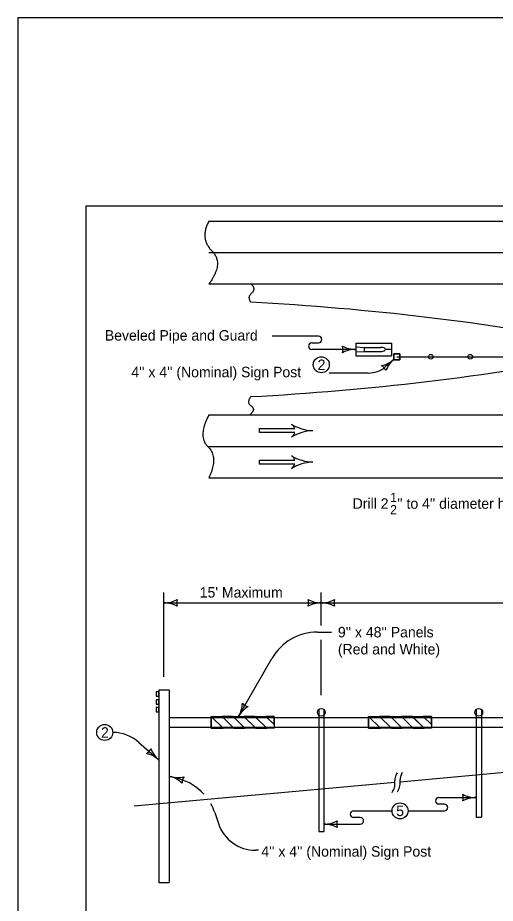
# Model space of a CAD drawing. Extents: x 228 to 3572, y -1307 to 1277.
# Drawn here: x 228 to 956, y -75 to 1277 of the extents above; entities that cross this region are included whole.
import ezdxf

# ---------------------------------------------------------------- set-up
doc = ezdxf.new("R2010")
doc.units = 0
for name, color, linetype in [('dsnShtPlotShapeBatchPrint', 7, 'Continuous'), ('dsnStdBorder', 7, 'Continuous'), ('dsnStdDimension', 7, 'Continuous'), ('Level 2', 7, 'Continuous'), ('Level 3', 7, 'Continuous')]:
    doc.layers.add(name, color=color, linetype=linetype)

msp = doc.modelspace()

# ---------------------------------------------------------------- linework, layer by layer
at = {"layer": 'dsnShtPlotShapeBatchPrint'}
msp.add_lwpolyline([(228, -1307), (3572, -1307), (3572, 1277), (228, 1277)], close=True, dxfattribs=at)
at = {"layer": 'dsnStdBorder'}
msp.add_lwpolyline([(332.5, 990), (3467.5, 990), (3467.5, -1020), (332.5, -1020)], close=True, dxfattribs=at)
at = {"layer": 'dsnStdDimension'}
for p, q in [((686.5, 791), (616.2, 791)), ((676.3, 780.9), (686.5, 780.9)), ((743.5, 770.7), (676.3, 770.7)), ((762.5, 734.6), (703, 734.6)), ((450.9, 270.8), (450.9, 399.9)), ((690.9, 349.5), (690.9, 399.9)), ((450.9, 383.9), (690.9, 383.9)), ((690.9, 383.9), (2130.9, 383.9)), ((685, 339.3), (706.4, 339.3)), ((690.9, 242.8), (690.9, 327.7)), ((564.7, 210.5), (615.6, 299.1)), ((412.7, 171), (442.9, 144.2)), ((870, 86.7), (926.9, 86.7)), ((878.5, 76.6), (868.4, 76.6)), ((528.4, 63.7), (534.1, 47)), ((740.2, 66.4), (798.6, 66.4)), ((750.3, 56.2), (740.2, 56.2)), ((823.1, 66.4), (878.5, 66.4)), ((694.9, 46.1), (750.3, 46.1))]:
    msp.add_line(p, q, dxfattribs=at)
for centre, radius, start, end in [((686.5, 786), 5.08, 270, 90), ((676.3, 775.8), 5.08, 90, 270), ((707.3, 770.7), 16.7, 342.2667, 17.7334), ((743.5, 813.9), 43.2, 241.9275, 270), ((743.5, 727.5), 43.2, 90, 118.0725), ((762.5, 774.6), 40, 270, 311.3965), ((772.8, 787.9), 43.2, 283.3279, 311.4004), ((774.2, 731.6), 16.7, 23.667, 59.1338), ((829.9, 723.2), 43.2, 131.4004, 159.4729), ((450.9, 427.1), 43.2, 270, 298.0725), ((450.9, 340.7), 43.2, 61.9275, 90), ((487.1, 383.9), 16.7, 162.2666, 197.7334), ((654.7, 383.9), 16.7, 342.2666, 17.7333), ((690.9, 427.1), 43.2, 241.9275, 270), ((690.9, 340.7), 43.2, 90, 118.0725), ((690.9, 427.1), 43.2, 270, 298.0725), ((690.9, 340.7), 43.2, 61.9275, 90), ((727.1, 383.9), 16.7, 162.2666, 197.7334), ((685, 259.3), 80, 90, 150.1271), ((527.3, 232), 43.2, 330.1265, 358.1989), ((582.8, 241.9), 16.7, 222.3931, 257.8598), ((602.2, 189), 43.2, 122.054, 150.1265), ((372.9, 126.1), 60, 48.4556, 90), ((415.8, 168.2), 16.7, 300.7265, 336.1932), ((414.3, 111.9), 43.2, 48.4599, 76.5324), ((471.5, 176.5), 43.2, 200.3874, 228.4599), ((472.1, 160.5), 43.2, 254.5401, 282.6126), ((449.1, 77.3), 43.2, 46.4677, 74.5401), ((452.7, 38.1), 80, 42.2764, 74.5518), ((495.5, 109.3), 16.7, 146.8068, 182.2735), ((870, 81.6), 5.08, 90, 270), ((890.7, 86.7), 16.7, 342.2666, 17.7333), ((926.9, 129.9), 43.2, 241.9275, 270), ((926.9, 43.5), 43.2, 90, 118.0725), ((452.7, 38.1), 80, 18.6748, 29.0674), ((878.5, 71.5), 5.08, 270, 90), ((740.2, 61.3), 5.08, 90, 270), ((750.3, 51.2), 5.08, 270, 90), ((590.9, 66.2), 60, 198.6726, 270), ((694.9, 89.3), 43.2, 270, 298.0725), ((694.9, 2.9), 43.2, 61.9275, 90), ((731.1, 46.1), 16.7, 162.2666, 197.7334)]:
    msp.add_arc(centre, radius, start, end, dxfattribs=at)
at = {"layer": 'Level 2'}
for p, q in [((519.5, 966.7), (2276.3, 966.7)), ((519.5, 918.7), (2276.3, 918.7)), ((519.5, 870.7), (2276.3, 870.7)), ((743.5, 780.3), (743.5, 761.1)), ((743.5, 780.3), (797.9, 780.3)), ((743.5, 774.6), (756.3, 773.9)), ((756.3, 773.9), (781, 773.9)), ((756.3, 773.9), (756.3, 767.5)), ((797.9, 770.7), (788.8, 770.7)), ((797.9, 780.3), (797.9, 761.1)), ((743.5, 766.9), (756.3, 767.5)), ((743.5, 761.1), (797.9, 761.1)), ((756.3, 767.5), (781, 767.5)), ((805.9, 759.5), (1989.9, 759.5)), ((801.4, 755.5), (788.9, 744.6)), ((519.5, 670.7), (2276.3, 670.7)), ((596.6, 649.8), (650.4, 649.8)), ((596.6, 643.7), (596.6, 649.8)), ((650.4, 643.7), (596.6, 643.7)), ((519.5, 622.7), (2276.3, 622.7)), ((596.6, 601.8), (650.4, 601.8)), ((596.6, 595.7), (596.6, 601.8)), ((650.4, 595.7), (596.6, 595.7)), ((519.5, 574.7), (2276.3, 574.7)), ((458.9, 250.8), (442.9, 250.8)), ((442.9, 250.8), (442.9, 77.1)), ((458.9, 250.8), (458.9, 78.6)), ((686.9, 220.8), (686.9, 99.1)), ((694.9, 220.8), (694.9, 99.9)), ((926.9, 220.8), (926.9, 120.8)), ((934.9, 220.8), (934.9, 121.5)), ((458.9, 208.8), (1118.9, 208.8)), ((522.9, 210.5), (541, 192.4)), ((539.6, 210.5), (557.7, 192.4)), ((556.3, 210.5), (574.4, 192.4)), ((573, 210.5), (591.1, 192.4)), ((589.7, 210.5), (607.7, 192.4)), ((606.4, 210.5), (618.9, 198)), ((762.9, 210.5), (781, 192.4)), ((779.6, 210.5), (797.7, 192.4)), ((796.3, 210.5), (814.4, 192.4)), ((813, 210.5), (831.1, 192.4)), ((829.6, 210.5), (847.7, 192.4)), ((846.4, 210.5), (858.9, 198)), ((458.9, 194.3), (1118.9, 194.3)), ((805, 121.3), (806.9, 124.5)), ((970.9, 124.8), (810.9, 110.3)), ((813, 122.1), (814.9, 125.3)), ((802.9, 109.6), (405.3, 73.7)), ((474, 115.2), (460.6, 118.9)), ((802.9, 105.9), (802.9, 113.3)), ((810.9, 106.6), (810.9, 114.1)), ((926.9, 120.8), (926.9, 56.6)), ((934.9, 121.5), (934.9, 56.6)), ((686.9, 99.1), (686.9, 34.9)), ((694.9, 99.9), (694.9, 34.9)), ((798.9, 94.7), (800.7, 97.9)), ((806.9, 95.4), (808.7, 98.6)), ((442.9, 77.1), (442.9, -42.9)), ((458.9, 78.6), (458.9, -42.9)), ((926.9, 56.6), (934.9, 56.6)), ((686.9, 34.9), (694.9, 34.9)), ((595.3, 6.2), (590.9, 6.2)), ((442.9, -42.9), (458.9, -42.9))]:
    msp.add_line(p, q, dxfattribs=at)
for points in [[(801.4, 764), (810.4, 764), (810.4, 755), (801.4, 755)], [(801.4, 755), (810.4, 755), (810.4, 764), (801.4, 764)], [(442.9, 248), (438.9, 248), (438.9, 241.5), (442.9, 241.5)], [(442.9, 236), (438.9, 236), (438.9, 229.5), (442.9, 229.5)], [(442.9, 224), (438.9, 224), (438.9, 217.5), (442.9, 217.5)], [(522.9, 210.5), (618.9, 210.5), (618.9, 192.4), (522.9, 192.4)], [(522.9, 210.5), (522.9, 192.4), (541, 192.4)], [(557.7, 192.4), (574.4, 192.4), (556.3, 210.5), (539.6, 210.5)], [(591.1, 192.4), (607.7, 192.4), (589.7, 210.5), (573, 210.5)], [(618.9, 198), (618.9, 210.5), (606.4, 210.5)], [(762.9, 210.5), (858.9, 210.5), (858.9, 192.4), (762.9, 192.4)], [(762.9, 210.5), (762.9, 192.4), (781, 192.4)], [(797.7, 192.4), (814.4, 192.4), (796.3, 210.5), (779.6, 210.5)], [(831.1, 192.4), (847.7, 192.4), (829.7, 210.5), (813, 210.5)], [(858.9, 198), (858.9, 210.5), (846.4, 210.5)]]:
    msp.add_lwpolyline(points, close=True, dxfattribs=at)
for centre, radius in [((690.9, 747.3), 12.2), ((857.9, 759.5), 3.56), ((917.9, 759.5), 3.56), ((690.9, 216.8), 6), ((930.9, 216.8), 6), ((360.6, 186.1), 12.2), ((810.9, 66.4), 12.2)]:
    msp.add_circle(centre, radius, dxfattribs=at)
for centre, radius, start, end in [((367.5, -3224.7), 4073.2, 79.3836, 86.9601), ((367.5, 4766.1), 4073.2, 273.0399, 280.6164), ((639.3, 646.7), 11.5, 15.4195, 58.2853), ((679.8, 712.2), 65.5, 238.2857, 268.3158), ((679.8, 581.2), 65.5, 91.6842, 121.7143), ((639.3, 646.7), 11.5, 301.7147, 344.5877), ((639.3, 598.7), 11.5, 15.4195, 58.2853), ((679.8, 664.2), 65.5, 238.2857, 268.3158), ((679.8, 533.2), 65.5, 91.6842, 121.7143), ((639.3, 598.7), 11.5, 301.7147, 344.5877), ((826.9, 114.1), 16, 150.0212, 180), ((818.9, 113.3), 16, 150.0327, 180), ((786.9, 105.9), 16, 329.9983, 0), ((794.9, 106.6), 16, 330.0004, 0)]:
    msp.add_arc(centre, radius, start, end, dxfattribs=at)
msp.add_ellipse((781, 770.7), major_axis=(7.77, 0), ratio=0.411692, start_param=4.712389, end_param=7.853982, dxfattribs=at)
for points in [[(519.5, 966.7), (505.2, 940), (542.9, 902.2), (519.5, 870.7)], [(583.5, 842.7), (578, 851.4), (592.3, 863), (583.4, 871)], [(583.5, 698.7), (576.3, 689.3), (591.4, 679.5), (582.5, 671.5)], [(519.5, 670.7), (501.8, 637.7), (534.4, 606.8), (519.5, 574.7)]]:
    msp.add_open_spline(points, degree=2, dxfattribs=at)

# ---------------------------------------------------------------- texts
at = {"layer": 'dsnStdDimension'}
for s, height, p in [('Beveled Pipe and Guard', 16, (360.8, 784.2)), ("4'' x 4'' (Nominal) Sign Post", 16, (401.2, 728.2)), ('Drill 2', 16, (738.7, 527.5)), ('1', 14, (795.8, 537.8)), ("'' to 4'' diameter hole thru crossover pavement for each post.", 16, (806.7, 527.5)), ('2', 14, (795.8, 519.1)), ("15' Maximum", 16, (505.5, 391.9)), ("9'' x 48'' Panels ", 16, (716.2, 331.2)), ('(Red and White)', 16, (716.2, 305.2)), ("4'' x 4'' (Nominal) Sign Post", 16, (599.4, -3.5))]:
    msp.add_text(s, height=height, dxfattribs=at).set_placement(p)
at = {"layer": 'Level 3'}
for s, p in [('2', (685.3, 739.3)), ('2', (355, 178.1)), ('5', (805.1, 58.4))]:
    msp.add_text(s, height=16, dxfattribs=at).set_placement(p)

doc.saveas('drawing.dxf')
